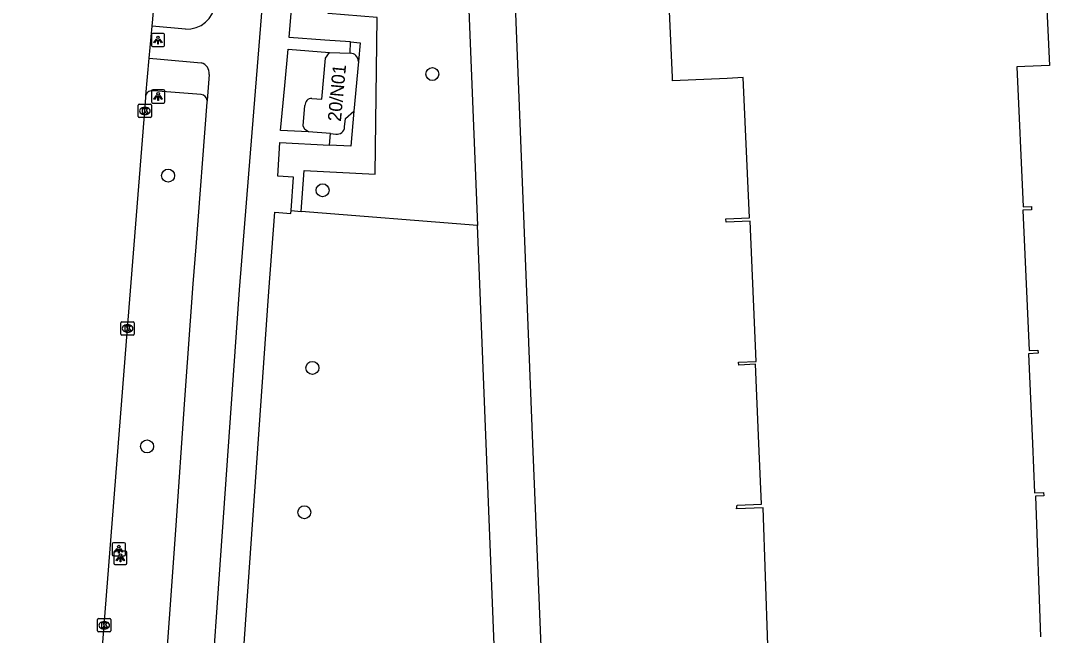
# Model space of a CAD drawing. Extents: x 161243 to 161752, y 384138 to 384885.
# Drawn here: x 161249.9 to 161327.5, y 384235.5 to 384281.9 of the extents above; entities that cross this region are included whole.
import ezdxf

# ---------------------------------------------------------------- set-up
doc = ezdxf.new("R2010")
doc.units = 0
for name, color, linetype in [('IMGEO_Boom', 7, 'Continuous'), ('IMGEO_Fietspad_gesloten', 7, 'Continuous'), ('IMGEO_Groenvoorziening', 7, 'Continuous'), ('IMGEO_Kolk', 7, 'Continuous'), ('IMGEO_Lichtpunt', 7, 'Continuous'), ('IMGEO_OVBaan_gesloten', 7, 'Continuous'), ('IMGEO_Pand', 7, 'Continuous'), ('IMGEO_Pand_nummerreeks', 7, 'Continuous'), ('IMGEO_Voetpad_open', 7, 'Continuous')]:
    doc.layers.add(name, color=color, linetype=linetype)

msp = doc.modelspace()

# ---------------------------------------------------------------- linework, layer by layer
at = {"layer": 'IMGEO_Boom'}
for centre in [(161280.983, 384277.833), (161261.061, 384270.183), (161272.71, 384269.077), (161271.937, 384255.694), (161259.472, 384249.773), (161271.331, 384244.819)]:
    msp.add_circle(centre, 0.489, dxfattribs=at)
at = {"layer": 'IMGEO_Fietspad_gesloten'}
for points in [[(161258.742, 384157.135), (161260.876, 384184.71), (161262.854, 384210.484), (161266.448, 384261.586), (161267.146, 384270.325), (161268.291, 384284.663), (161268.569, 384287.683), (161268.583, 384287.814)], [(161262.361, 384281.225), (161259.867, 384281.454)], [(161259.641, 384279.02), (161260.484, 384278.968), (161263.557, 384278.689)], [(161264.144, 384277.795), (161263.994, 384275.849)], [(161263.994, 384275.849), (161263.983, 384275.709), (161263.143, 384264.813), (161262.927, 384262.016), (161262.305, 384253.304), (161261.604, 384243.474), (161259.279, 384210.879), (161257.318, 384184.907), (161257.099, 384182.165), (161256.945, 384180.975), (161255.727, 384175.693), (161255.111, 384172.583), (161254.402, 384168.209), (161253.797, 384163.617), (161252.937, 384155.312)]]:
    msp.add_lwpolyline(points, dxfattribs=at)
for centre, radius, start, end in [((161262.504, 384283.328), 2.108, 266.10795, 355.43441), ((161263.347, 384277.911), 0.806, 351.71384, 74.86393)]:
    msp.add_arc(centre, radius, start, end, dxfattribs=at)
at = {"layer": 'IMGEO_Groenvoorziening'}
for points in [[(161300.059, 384300.607), (161300.109, 384299.408), (161291.319, 384298.89), (161286.795, 384293.851), (161288.542, 384250), (161289.176, 384234.089), (161286.463, 384228.528), (161287.535, 384200.127), (161274.519, 384199.728), (161272.888, 384197.971)], [(161283.264, 384294.561), (161284.385, 384266.432)], [(161271.096, 384267.486), (161271.311, 384270.579), (161276.661, 384270.286), (161276.83, 384282.104), (161273.116, 384282.399), (161274.077, 384289.358), (161278.317, 384291.304)], [(161274.803, 384280.25), (161275.543, 384280.195), (161275.415, 384278.786)], [(161275.073, 384275.029), (161274.833, 384272.389), (161273.226, 384272.477)], [(161270.33, 384267.547), (161271.096, 384267.486)], [(161284.385, 384266.432), (161271.096, 384267.486)], [(161272.718, 384203.175), (161283.905, 384203.517), (161282.932, 384229.273), (161285.644, 384234.831), (161284.385, 384266.432)]]:
    msp.add_lwpolyline(points, dxfattribs=at)
at = {"layer": 'IMGEO_Kolk'}
for p, q in [((161258.811, 384274.628), (161258.811, 384275.48)), ((161258.886, 384275.554), (161259.738, 384275.554)), ((161259.299, 384275.334), (161259.324, 384275.334)), ((161259.812, 384275.48), (161259.812, 384274.628)), ((161259.738, 384274.554), (161258.886, 384274.554)), ((161259.322, 384274.774), (161259.297, 384274.774)), ((161257.501, 384258.238), (161257.501, 384259.09)), ((161257.576, 384259.164), (161258.428, 384259.164)), ((161257.989, 384258.944), (161258.014, 384258.944)), ((161258.502, 384259.09), (161258.502, 384258.238)), ((161258.428, 384258.164), (161257.576, 384258.164)), ((161258.012, 384258.384), (161257.987, 384258.384)), ((161255.739, 384235.873), (161255.739, 384236.725)), ((161255.814, 384236.799), (161256.666, 384236.799)), ((161256.227, 384236.579), (161256.252, 384236.579)), ((161256.74, 384236.725), (161256.74, 384235.873)), ((161256.666, 384235.799), (161255.814, 384235.799)), ((161256.25, 384236.019), (161256.225, 384236.019))]:
    msp.add_line(p, q, dxfattribs=at)
for points in [[(161258.811, 384274.628), (161258.811, 384275.48)], [(161258.886, 384275.554), (161259.738, 384275.554)], [(161259.132, 384275.254), (161259.255, 384275.254), (161259.255, 384275.103), (161259.385, 384275.254), (161259.549, 384275.254), (161259.403, 384275.103), (161259.556, 384274.854), (161259.404, 384274.854), (161259.319, 384275.018), (161259.255, 384274.951), (161259.255, 384274.854), (161259.132, 384274.854), (161259.132, 384275.254)], [(161259.812, 384275.48), (161259.812, 384274.628)], [(161259.738, 384274.554), (161258.886, 384274.554)], [(161257.501, 384258.238), (161257.501, 384259.09)], [(161257.576, 384259.164), (161258.428, 384259.164)], [(161258.502, 384259.09), (161258.502, 384258.238)], [(161258.428, 384258.164), (161257.576, 384258.164)], [(161257.822, 384258.864), (161257.945, 384258.864), (161257.945, 384258.713), (161258.075, 384258.864), (161258.239, 384258.864), (161258.093, 384258.713), (161258.246, 384258.464), (161258.094, 384258.464), (161258.009, 384258.628), (161257.945, 384258.561), (161257.945, 384258.464), (161257.822, 384258.464), (161257.822, 384258.864)], [(161255.739, 384235.873), (161255.739, 384236.725)], [(161255.814, 384236.799), (161256.666, 384236.799)], [(161256.06, 384236.499), (161256.183, 384236.499), (161256.183, 384236.348), (161256.313, 384236.499), (161256.477, 384236.499), (161256.331, 384236.348), (161256.484, 384236.099), (161256.332, 384236.099), (161256.247, 384236.263), (161256.183, 384236.196), (161256.183, 384236.099), (161256.06, 384236.099), (161256.06, 384236.499)], [(161256.74, 384236.725), (161256.74, 384235.873)], [(161256.666, 384235.799), (161255.814, 384235.799)]]:
    msp.add_lwpolyline(points, dxfattribs=at)
for centre, start, end in [((161258.888, 384275.478), 91.55205, 178.44795), ((161258.888, 384275.478), 91.55205, 178.44795), ((161259.736, 384275.478), 1.55205, 88.44795), ((161259.736, 384275.478), 1.55205, 88.44795), ((161258.888, 384274.63), 181.55205, 268.44795), ((161258.888, 384274.63), 181.55205, 268.44795), ((161259.736, 384274.63), 271.55205, 358.44795), ((161259.736, 384274.63), 271.55205, 358.44795), ((161257.578, 384259.088), 91.55205, 178.44795), ((161257.578, 384259.088), 91.55205, 178.44795), ((161258.426, 384259.088), 1.55205, 88.44795), ((161258.426, 384259.088), 1.55205, 88.44795), ((161257.578, 384258.24), 181.55205, 268.44795), ((161257.578, 384258.24), 181.55205, 268.44795), ((161258.426, 384258.24), 271.55205, 358.44795), ((161258.426, 384258.24), 271.55205, 358.44795), ((161255.816, 384236.723), 91.55205, 178.44795), ((161255.816, 384236.723), 91.55205, 178.44795), ((161256.664, 384236.723), 1.55205, 88.44795), ((161256.664, 384236.723), 1.55205, 88.44795), ((161255.816, 384235.875), 181.55205, 268.44795), ((161255.816, 384235.875), 181.55205, 268.44795), ((161256.664, 384235.875), 271.55205, 358.44795), ((161256.664, 384235.875), 271.55205, 358.44795)]:
    msp.add_arc(centre, 0.0765, start, end, dxfattribs=at)
for centre, major_axis, ratio, start_param, end_param in [((161259.298, 384275.054), (-0.387, 0.002), 0.722429, 4.712389, 7.853982), ((161259.323, 384275.054), (-0.39, 0.002), 0.717154, 1.570796, 4.712389), ((161257.988, 384258.664), (-0.387, 0.002), 0.722429, 4.712389, 7.853982), ((161258.013, 384258.664), (-0.39, 0.002), 0.717154, 1.570796, 4.712389), ((161256.226, 384236.299), (-0.387, 0.002), 0.722429, 4.712389, 7.853982), ((161256.251, 384236.299), (-0.39, 0.002), 0.717154, 1.570796, 4.712389)]:
    msp.add_ellipse(centre, major_axis=major_axis, ratio=ratio, start_param=start_param, end_param=end_param, dxfattribs=at)
at = {"layer": 'IMGEO_Lichtpunt'}
for p, q in [((161259.797, 384280.803), (161259.797, 384279.996)), ((161259.797, 384280.803), (161259.797, 384279.996)), ((161260.699, 384280.898), (161259.891, 384280.898)), ((161260.699, 384280.898), (161259.891, 384280.898)), ((161260.793, 384279.996), (161260.793, 384280.803)), ((161260.793, 384279.996), (161260.793, 384280.803)), ((161259.891, 384279.902), (161260.699, 384279.902)), ((161259.891, 384279.902), (161260.699, 384279.902)), ((161259.806, 384276.553), (161259.806, 384275.746)), ((161259.806, 384276.553), (161259.806, 384275.746)), ((161260.708, 384276.648), (161259.9, 384276.648)), ((161260.708, 384276.648), (161259.9, 384276.648)), ((161260.802, 384275.746), (161260.802, 384276.553)), ((161260.802, 384275.746), (161260.802, 384276.553)), ((161259.9, 384275.652), (161260.708, 384275.652)), ((161259.9, 384275.652), (161260.708, 384275.652)), ((161256.84, 384242.428), (161256.84, 384241.621)), ((161256.84, 384242.428), (161256.84, 384241.621)), ((161257.742, 384242.523), (161256.934, 384242.523)), ((161257.742, 384242.523), (161256.934, 384242.523)), ((161257.861, 384241.877), (161257.053, 384241.877)), ((161257.861, 384241.877), (161257.053, 384241.877)), ((161257.836, 384241.621), (161257.836, 384242.428)), ((161257.836, 384241.621), (161257.836, 384242.428)), ((161256.934, 384241.527), (161257.742, 384241.527)), ((161256.934, 384241.527), (161257.742, 384241.527)), ((161256.959, 384241.782), (161256.959, 384240.975)), ((161256.959, 384241.782), (161256.959, 384240.975)), ((161257.955, 384240.975), (161257.955, 384241.782)), ((161257.955, 384240.975), (161257.955, 384241.782)), ((161257.053, 384240.881), (161257.861, 384240.881)), ((161257.053, 384240.881), (161257.861, 384240.881))]:
    msp.add_line(p, q, dxfattribs=at)
for points in [[(161260.171, 384280.467), (161260.21, 384280.439), (161260.022, 384280.177), (161259.984, 384280.204), (161260.171, 384280.467)], [(161260.273, 384280.419), (161260.32, 384280.419), (161260.32, 384280.097), (161260.273, 384280.097), (161260.273, 384280.419)], [(161260.383, 384280.439), (161260.421, 384280.466), (161260.608, 384280.204), (161260.569, 384280.176), (161260.383, 384280.439)], [(161260.18, 384276.217), (161260.219, 384276.189), (161260.031, 384275.927), (161259.993, 384275.954), (161260.18, 384276.217)], [(161260.282, 384276.169), (161260.329, 384276.169), (161260.329, 384275.847), (161260.282, 384275.847), (161260.282, 384276.169)], [(161260.392, 384276.189), (161260.43, 384276.216), (161260.617, 384275.954), (161260.578, 384275.926), (161260.392, 384276.189)], [(161257.214, 384242.092), (161257.253, 384242.064), (161257.065, 384241.802), (161257.027, 384241.829), (161257.214, 384242.092)], [(161257.316, 384242.044), (161257.363, 384242.044), (161257.363, 384241.722), (161257.316, 384241.722), (161257.316, 384242.044)], [(161257.426, 384242.064), (161257.464, 384242.091), (161257.651, 384241.829), (161257.612, 384241.801), (161257.426, 384242.064)], [(161257.333, 384241.446), (161257.372, 384241.418), (161257.184, 384241.156), (161257.146, 384241.183), (161257.333, 384241.446)], [(161257.435, 384241.398), (161257.482, 384241.398), (161257.482, 384241.076), (161257.435, 384241.076), (161257.435, 384241.398)], [(161257.545, 384241.418), (161257.583, 384241.445), (161257.77, 384241.183), (161257.731, 384241.155), (161257.545, 384241.418)]]:
    msp.add_lwpolyline(points, dxfattribs=at)
for centre in [(161260.296, 384280.601), (161260.305, 384276.351), (161257.339, 384242.226), (161257.458, 384241.58)]:
    msp.add_circle(centre, 0.0994, dxfattribs=at)
for centre, start, end in [((161259.891, 384280.803), 90, 180), ((161259.891, 384280.803), 90, 180), ((161260.699, 384280.803), 0, 90), ((161260.699, 384280.803), 0, 90), ((161259.891, 384279.996), 180, 270), ((161259.891, 384279.996), 180, 270), ((161260.699, 384279.996), 270, 0), ((161260.699, 384279.996), 270, 360), ((161259.9, 384276.553), 90, 180), ((161259.9, 384276.553), 90, 180), ((161260.708, 384276.553), 0, 90), ((161260.708, 384276.553), 0, 90), ((161259.9, 384275.746), 180, 270), ((161259.9, 384275.746), 180, 270), ((161260.708, 384275.746), 270, 0), ((161260.708, 384275.746), 270, 360), ((161256.934, 384242.428), 90, 180), ((161256.934, 384242.428), 90, 180), ((161257.053, 384241.782), 90, 180), ((161257.053, 384241.782), 90, 180), ((161257.742, 384242.428), 0, 90), ((161257.742, 384242.428), 0, 90), ((161257.861, 384241.782), 0, 90), ((161257.861, 384241.782), 0, 90), ((161256.934, 384241.621), 180, 270), ((161256.934, 384241.621), 180, 270), ((161257.742, 384241.621), 270, 0), ((161257.742, 384241.621), 270, 360), ((161257.053, 384240.975), 180, 270), ((161257.053, 384240.975), 180, 270), ((161257.861, 384240.975), 270, 0), ((161257.861, 384240.975), 270, 360)]:
    msp.add_arc(centre, 0.0946, start, end, dxfattribs=at)
at = {"layer": 'IMGEO_OVBaan_gesloten'}
for points in [[(161259.867, 384281.454), (161259.915, 384281.975), (161259.918, 384282.004), (161260.014, 384283.129), (161261.613, 384299.182), (161261.706, 384299.932)], [(161259.641, 384279.02), (161259.867, 384281.454)], [(161259.381, 384276.22), (161259.641, 384279.02)], [(161249.934, 384156.079), (161249.949, 384156.206), (161250.106, 384158.053), (161251.316, 384173.143), (161251.591, 384176.567), (161253.117, 384195.97), (161254.778, 384217.347), (161256.24, 384236.299), (161258.002, 384258.664), (161259.312, 384275.054), (161259.367, 384276.07), (161259.381, 384276.22)]]:
    msp.add_lwpolyline(points, dxfattribs=at)
at = {"layer": 'IMGEO_Pand'}
for points in [[(161306.273, 384234.801), (161305.917, 384245.154), (161303.929, 384245.085), (161303.962, 384245.349), (161305.799, 384245.413), (161305.601, 384250), (161305.343, 384255.962), (161304.084, 384255.907), (161304.074, 384256.121), (161305.404, 384256.179), (161304.937, 384266.744), (161303.127, 384266.665), (161303.116, 384266.933), (161304.897, 384267.011), (161304.431, 384277.563), (161303.212, 384277.509), (161299.098, 384277.327), (161299.087, 384277.57), (161298.816, 384283.71)], [(161327.251, 384284.365), (161327.513, 384278.476), (161325.648, 384278.393), (161325.057, 384278.367), (161325.522, 384267.828), (161326.151, 384267.855), (161326.162, 384267.613), (161325.509, 384267.585), (161325.976, 384256.993), (161326.644, 384257.022), (161326.655, 384256.791), (161325.934, 384256.76), (161326.23, 384250), (161326.393, 384246.283), (161327.072, 384246.307), (161327.081, 384246.049), (161326.465, 384246.028), (161326.83, 384235.436)], [(161271.895, 384275.997), (161272.641, 384275.93), (161272.923, 384279.031), (161273.24, 384279.465)], [(161273.24, 384279.465), (161274.791, 384279.413)], [(161275.415, 384278.786), (161275.073, 384275.029)], [(161271.652, 384273.491), (161271.373, 384273.645), (161271.234, 384273.931), (161271.375, 384275.46)], [(161274.366, 384273.847), (161274.424, 384274.489), (161275.073, 384275.029)], [(161273.291, 384273.347), (161271.652, 384273.491)], [(161273.291, 384273.347), (161273.707, 384273.311)]]:
    msp.add_lwpolyline(points, dxfattribs=at)
for centre, radius, start, end in [((161274.761, 384278.759), 0.654, 2.32184, 87.40336), ((161271.894, 384275.478), 0.519, 89.89143, 181.95142), ((161273.793, 384273.878), 0.574, 261.36298, 356.88363)]:
    msp.add_arc(centre, radius, start, end, dxfattribs=at)
at = {"layer": 'IMGEO_Voetpad_open'}
for points in [[(161274.803, 384280.25), (161272.878, 384280.394), (161270.194, 384280.594), (161270.995, 384290.346)], [(161274.791, 384279.413), (161274.803, 384280.25)], [(161271.652, 384273.491), (161269.538, 384273.591), (161269.854, 384276.964), (161270.111, 384279.698), (161273.24, 384279.465)], [(161263.559, 384276.285), (161259.964, 384276.56)], [(161273.226, 384272.477), (161273.291, 384273.347)], [(161270.33, 384267.547), (161270.525, 384270.075), (161269.327, 384270.147), (161269.486, 384272.682), (161273.226, 384272.477)], [(161264.495, 384202.929), (161265.049, 384210.182), (161268.653, 384261.442), (161269.116, 384267.426), (161270.314, 384267.335), (161270.33, 384267.547)]]:
    msp.add_lwpolyline(points, dxfattribs=at)
for centre, start, end in [((161259.839, 384276.105), 74.56857, 165.93208), ((161263.523, 384275.814), 4.23006, 85.63838)]:
    msp.add_arc(centre, 0.472, start, end, dxfattribs=at)

# ---------------------------------------------------------------- texts
at = {"layer": 'IMGEO_Pand_nummerreeks'}
msp.add_text('20/N01', height=1, rotation=84.7331, dxfattribs=at).set_placement((161274.088, 384274.221))

doc.saveas('drawing.dxf')
